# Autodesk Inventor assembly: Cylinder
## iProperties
Created: 2001-12
Part Number: Cylinder
Document SubType Name: Assembly
Designer: Tobben
Control State: 0
Master: False
Checked Out: False
Shininess: 64.0
Length Units: 11269
Angle Units: 11279
Time Units: 11290
Mass Units: 11283
Length Display Precision: 3
Angle Display Precision: 2
Density: 0.0
Volumn: 0.0
Area: 0.0
PropertySet Name: Model Information
Author: Tobben
